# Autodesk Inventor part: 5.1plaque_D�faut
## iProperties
Created: 2011-01
Part Number: 5.1plaque_D�faut
Document SubType Name: Modeling
Designer: eric
Density: 1 g/cm^3
Mass: 7.87973 g
Surface Area: 64.1239 cm^2
Volume: 7.87973 cm^3
Author: eric
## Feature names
1. Base1
